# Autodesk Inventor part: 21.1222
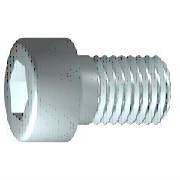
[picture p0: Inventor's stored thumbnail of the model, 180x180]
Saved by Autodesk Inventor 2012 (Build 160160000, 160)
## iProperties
Created: 2006-02
Part Number: 21.1222
Material: Steel, Mild
Description: M5 X 20 SHCS
Document SubType Name: Modeling
Standard: DIN 7984
Designer: Andy Moles
Standards Organization: DIN
Language: en-US
Size Designation: M5 x 20
Categories: <MemberInstance><Categories><Category DisplayName="Fasteners" InternalName="e4da775c-781d-43d5-af7c-5136215cf5a6" Mnemonic="FSTN"><Category DisplayName="Bolts"
Density: 7.86 g/cm^3
Mass: 4.43338 g
Surface Area: 5.40621 cm^2
Volume: 0.564044 cm^3
Author: Andy Moles
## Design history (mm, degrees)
body "Solid1"
workplane "Work Plane1"
revolve "Body" stored, may be unused: angle "d10" = 90 deg
sketch "Sketch2"
  geometry: L1 (0, -5.1)-(0, 6.8) reference; L2 (-5.1, 0)-(6.8, 0) reference; L3 (1.732, 0)-(0.866, -1.5); L4 (0.866, -1.5)-(-0.866, -1.5); L5 (-0.866, -1.5)-(-1.732, 0); L6 (-1.732, 0)-(-0.866, 1.5); L7 (-0.866, 1.5)-(0.866, 1.5); L8 (0.866, 1.5)-(1.732, 0); 2 further points
  constraints: 12 end point, 1 coincident, 1 horizontal alignment, 1 point on line, 12 other
extrude "Slot" join sketch "Sketch2" stored distance "d11" = 10; taper "d12" = 0 deg
fillet "Fillet1" dims "d17" = 0.5 (= RR)
feature "Thread" dims "d13" = 20, "d14" = 0
chamfer "Chamfer1" distance "d15" = 0.49076 (= -0.5 x SPD + 0.5 x GD); stored, may be unused: second distance "d16" = 0.49076 (= GUL), angle "d27" = 45 deg
sketch "Sketch1"
  geometry: L1 (0.2, 0)-(20, 0); L2 (20, 0)-(20, 2.5); L3 (20, 2.5)-(2.4, 2.5); L4 (2.4, 2.5)-(1.909, 2.5); L5 (1.909, 2.5)-(0, 2.5); L6 (0, 2.5)-(0, 4.25); L7 (0, 4.25)-(-3.5, 4.25); L8 (-3.5, 4.25)-(-3.5, 1.732); L9 (-3.5, 1.732)-(-0.8, 1.732); L10 (-0.8, 1.732)-(0.2, 0); L11 (-5.85, 0)-(27.05, 0) reference; L12 (0, -0.425)-(0, 5.525) reference; L13 (2.4, 2.5)-(0, 2.5)
  constraints: 22 end point, 6 parallel, 2 collinear, 2 perpendicular, 1 horizontal, 1 point on line
  dimensions: "d1" = 17.6 distance from line of L3.end L2 (= GEL); "d2" = 0.49086 distance of L4.end L3.end (computed from GAL); "d3" = 3.5 distance between parallel lines of L8 L6 (= KOH); "d4" = 2.7 distance of L8.end L9.end (= INTI); "d5" = 60 deg angle of L10 L1; "d6" = 5 diameter of L3 L1 (= GD); "d7" = 5 diameter of L5 L1 (= BDM); "d8" = 3.4641 diameter of L9 L1 (= 1.1547 x SW); "d9" = 8.5 diameter of L7 L1 (= KOD); "d26" = 20 distance between parallel lines of L12 L2 (= NLG)
other parameters: "GD" = 5 (= NND) [user parameter; used in 2 equation terms], "NLG" = 20 [user parameter; used in 1 equation term], "GEL" = 17.6 [user parameter; used in 1 equation term], "KOD" = 8.5 [user parameter; used in 1 equation term], "KOH" = 3.5 [user parameter; used in 1 equation term], "INTI" = 2.7 [user parameter; used in 1 equation term], "GAL" = 0.49076 (= 0.61345 x PTC) [user parameter; used in 1 equation term], "GUL" = 0.49076 (= 0.61345 x PTC) [user parameter; used in 1 equation term], "BDM" = 5 (= NND) [user parameter; used in 1 equation term], "SW" = 3 [user parameter; used in 2 equation terms], "RR" = 0.5 [user parameter; used in 1 equation term], "SPD" = 4.01848 (= NND - 1.2269 x PTC) [user parameter; used in 1 equation term], "d19" = 0, "d28" = 0, "d29" = 0, "TOA" = 30 deg [user parameter], "GD1" = 4.01848 (= THREADDIA - 1.2269 x PTC) [user parameter], "THREADDIA" = 5 [user parameter; used in 1 equation term], "FAWI" = 45 deg [user parameter], "ANG" = 120 deg [user parameter], "TPU" = 12.5 (computed from PTC) [user parameter], "PTC" = 0.8 [user parameter; used in 5 equation terms], "NND" = 5 [user parameter; used in 3 equation terms], "E0" = 3.465 (= 1.155 x SW) [user parameter]
